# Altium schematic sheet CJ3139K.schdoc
size 127 x 101 mm
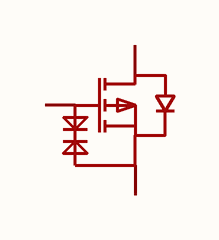
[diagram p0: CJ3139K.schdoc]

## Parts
Q?  cj3139k_c70022  [SOT-723_L1.2-W0.8-P0.40-LS1.2-BR]  (value not drawn)

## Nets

Not connected (* = marked no-connect by the designer): Q? 1(G) 2(S) 3(D)

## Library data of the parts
Q? = cj3139k_c70022: 数量:1个P沟道;漏源电压(Vdss):20V;连续漏极电流(Id):660mA;导通电阻(RDS(on)):520mΩ@4.5V;耗散功率(Pd):150mW;阈值电压(Vgs(th)):350mV;; Manufacturer: CJ(江苏长电/长晶); AddInBom: yes; ModelId: abccde1e67074d7481274a37cf5c97f0; ModelName: SOT-723-3P_L1.2-W0.8-H0.6-LS1.2-P0.40; ModelTransform: 47.244,47.244,0,180,0,0,0,0,0; Number: 1个P沟道; Drain to Source Voltage: 20V; Current - Continuous Drain(Id): 660mA; Pd - Power Dissipation: 150mW; Gate Threshold Voltage (Vgs(th)): 350mV; Input Capacitance(Ciss): 170pF; Reverse Transfer Capacitance (Crss@Vds): 15pF; Type: P沟道; Vgs: ±12V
